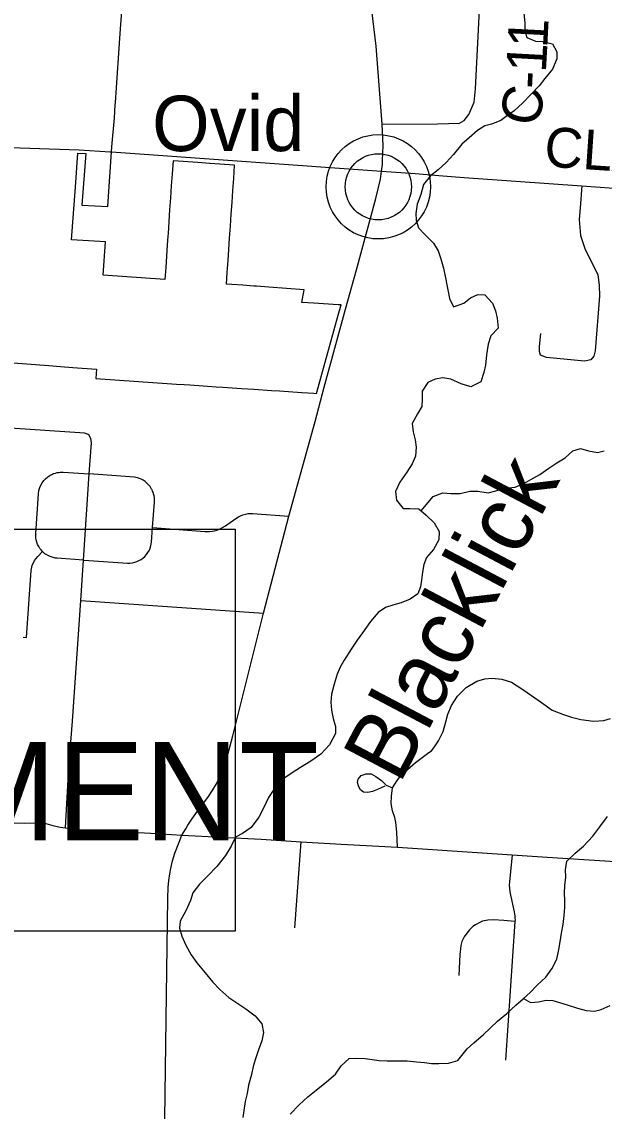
# Model space of a CAD drawing. Extents: x 208586767.6 to 208586821.4, y -134301046.9 to -134301022.9.
# Drawn here: x 208586783.069 to 208586783.899, y -134301029.209 to -134301027.656 of the extents above; entities that cross this region are included whole.
import ezdxf

# ---------------------------------------------------------------- set-up
doc = ezdxf.new("R2010")
doc.units = 0
for name, color, linetype in [('GM_X_Corporation', 7, 'Continuous'), ('GM_X_County_Road', 7, 'Continuous'), ('GM_X_County_Road_Text', 7, 'Continuous'), ('GM_X_Minor_River', 7, 'Continuous'), ('GM_X_Minor_River_Text', 7, 'Continuous'), ('GM_X_Township_Road', 7, 'Continuous'), ('GM_X_Unincorporated', 7, 'Continuous'), ('GM_X_Unincorporated_Location', 7, 'Continuous'), ('GM_X_Unincorporated_Text', 7, 'Continuous'), ('SH_Text', 7, 'Continuous')]:
    doc.layers.add(name, color=color, linetype=linetype)

msp = doc.modelspace()

# ---------------------------------------------------------------- linework, layer by layer
at = {"layer": 'GM_X_Corporation'}
msp.add_lwpolyline([(208586783.0375, -134301028.1406), (208586783.1069, -134301028.1457), (208586783.124, -134301028.147), (208586783.1414, -134301028.1483), (208586783.1752, -134301028.1508), (208586783.1743, -134301028.1644), (208586783.2892, -134301028.1721), (208586783.3002, -134301028.1729), (208586783.3081, -134301028.1734), (208586783.327, -134301028.1746), (208586783.3459, -134301028.1759), (208586783.3553, -134301028.1766), (208586783.3818, -134301028.1783), (208586783.3995, -134301028.1795), (208586783.4246, -134301028.1812), (208586783.436, -134301028.182), (208586783.4678, -134301028.1841), (208586783.4851, -134301028.1853), (208586783.489, -134301028.1855), (208586783.5199, -134301028.0739), (208586783.5238, -134301028.0594), (208586783.5197, -134301028.0591), (208586783.4849, -134301028.0567), (208586783.4681, -134301028.0556), (208586783.4711, -134301028.0376), (208586783.4209, -134301028.0339), (208586783.4032, -134301028.0327), (208586783.3995, -134301028.0324), (208586783.384, -134301028.0313), (208586783.3682, -134301028.0301), (208586783.3604, -134301028.0296), (208586783.3615, -134301028.0132), (208586783.3627, -134301027.9962), (208586783.3638, -134301027.9802), (208586783.3649, -134301027.9641), (208586783.3661, -134301027.9471), (208586783.3673, -134301027.9301), (208586783.3684, -134301027.9131), (208586783.3696, -134301027.8961), (208586783.3708, -134301027.8791), (208586783.3721, -134301027.8602), (208586783.3366, -134301027.8575), (208586783.3196, -134301027.8563), (208586783.2842, -134301027.8537), (208586783.2829, -134301027.8725), (208586783.2818, -134301027.8896), (208586783.2806, -134301027.9066), (208586783.2794, -134301027.9236), (208586783.2783, -134301027.9406), (208586783.2771, -134301027.9576), (208586783.2768, -134301027.9615), (208586783.276, -134301027.9736), (208586783.2749, -134301027.9897), (208586783.2738, -134301028.0058), (208586783.2725, -134301028.0232), (208586783.1845, -134301028.0168), (208586783.188, -134301027.9694), (208586783.1393, -134301027.9664), (208586783.145, -134301027.8912), (208586783.1486, -134301027.8428), (208586783.1486, -134301027.8428), (208586783.1598, -134301027.8435), (208586783.1541, -134301027.9169), (208586783.1913, -134301027.9191), (208586783.1972, -134301027.834), (208586783.2006, -134301027.7926), (208586783.2019, -134301027.7741), (208586783.2021, -134301027.7709), (208586783.2036, -134301027.7498), (208586783.205, -134301027.7286), (208586783.2065, -134301027.7074), (208586783.208, -134301027.6863), (208586783.2094, -134301027.6657), (208586783.2111, -134301027.6408)], dxfattribs=at)
at = {"layer": 'GM_X_County_Road'}
msp.add_line((208586783.1652, -134301027.8391), (208586783.1948, -134301027.8409), dxfattribs=at)
for points in [[(208586783.5826, -134301027.8014), (208586783.574, -134301027.6903), (208586783.5505, -134301027.4964), (208586783.5287, -134301027.2902), (208586783.5223, -134301027.2238)], [(208586783.5826, -134301027.8014), (208586783.6614, -134301027.8011), (208586783.6926, -134301027.8), (208586783.6994, -134301027.7964), (208586783.7062, -134301027.7879), (208586783.7138, -134301027.7703), (208586783.7156, -134301027.7514), (208586783.7306, -134301027.4507)], [(208586783.5817, -134301027.8687), (208586783.5829, -134301027.8591), (208586783.5831, -134301027.8531), (208586783.5838, -134301027.8322), (208586783.5826, -134301027.8014)], [(208586783.0158, -134301027.8351), (208586783.0232, -134301027.834), (208586783.1505, -134301027.8382), (208586783.1652, -134301027.8391)], [(208586783.1948, -134301027.8409), (208586783.1967, -134301027.8411), (208586783.5817, -134301027.8687)], [(208586783.4131, -134301028.4986), (208586783.4496, -134301028.3604), (208586783.4867, -134301028.2254), (208586783.4997, -134301028.1766), (208586783.5304, -134301028.0655), (208586783.5459, -134301028.0093), (208586783.5736, -134301027.9076), (208586783.5799, -134301027.8798), (208586783.5817, -134301027.8687)], [(208586783.5817, -134301027.8687), (208586783.6297, -134301027.8721), (208586783.6689, -134301027.8754), (208586783.6996, -134301027.8776)], [(208586783.6996, -134301027.8776), (208586783.773, -134301027.8829), (208586783.867, -134301027.8895), (208586783.9974, -134301027.8988), (208586784.018, -134301027.9003), (208586784.1319, -134301027.9081), (208586784.1979, -134301027.9129), (208586784.2562, -134301027.9169), (208586784.5033, -134301027.9324), (208586784.6185, -134301027.94), (208586784.7204, -134301027.9474)], [(208586783.2724, -134301029.22), (208586783.2744, -134301029.0773), (208586783.277, -134301028.9052), (208586783.2775, -134301028.89), (208586783.2784, -134301028.88), (208586783.2796, -134301028.8704), (208586783.2809, -134301028.8629), (208586783.2836, -134301028.8517), (208586783.2869, -134301028.8409), (208586783.293, -134301028.8253), (208586783.297, -134301028.8153), (208586783.3023, -134301028.8062), (208586783.3053, -134301028.8011), (208586783.311, -134301028.7924), (208586783.3169, -134301028.7845), (208586783.3349, -134301028.7601), (208586783.3411, -134301028.7508), (208586783.346, -134301028.7421), (208586783.3543, -134301028.7247), (208586783.3572, -134301028.7172), (208586783.3603, -134301028.7074), (208586783.3695, -134301028.6735), (208586783.3851, -134301028.6107), (208586783.4131, -134301028.4986)]]:
    msp.add_lwpolyline(points, dxfattribs=at)
at = {"layer": 'GM_X_Minor_River'}
for points in [[(208586783.7844, -134301027.6427), (208586783.7858, -134301027.6575), (208586783.7861, -134301027.6685), (208586783.7887, -134301027.678), (208586783.8012, -134301027.6834), (208586783.811, -134301027.6838), (208586783.8255, -134301027.6869), (208586783.8315, -134301027.6984), (208586783.8318, -134301027.7086), (208586783.8256, -134301027.723), (208586783.8145, -134301027.7366), (208586783.8065, -134301027.7468), (208586783.7943, -134301027.7592), (208586783.7824, -134301027.7717), (208586783.7706, -134301027.7826), (208586783.761, -134301027.7894), (208586783.7515, -134301027.7966), (208586783.7386, -134301027.8014), (208586783.7287, -134301027.804), (208586783.7184, -134301027.8108), (208586783.7066, -134301027.8213), (208586783.6959, -134301027.83), (208586783.6844, -134301027.8447), (208586783.6737, -134301027.8561), (208586783.6623, -134301027.8666), (208586783.6512, -134301027.8753), (208586783.6413, -134301027.8874), (208586783.6374, -134301027.9018), (208586783.6324, -134301027.9158), (208586783.6304, -134301027.929), (208586783.6311, -134301027.9385), (208586783.6344, -134301027.9496), (208586783.6431, -134301027.9591), (208586783.6555, -134301027.9713), (208586783.6623, -134301027.9824), (208586783.666, -134301027.9934), (208586783.6701, -134301028.0071), (208586783.6727, -134301028.0208), (208586783.6749, -134301028.0306), (208586783.6767, -134301028.0401), (208586783.6786, -134301028.05), (208586783.6842, -134301028.0622), (208586783.699, -134301028.0566), (208586783.7086, -134301028.0494), (208586783.7188, -134301028.0446), (208586783.7287, -134301028.045), (208586783.74, -134301028.0568), (208586783.7441, -134301028.0675), (208586783.7467, -134301028.0781), (208586783.7478, -134301028.0926), (208586783.7374, -134301028.1035), (208586783.7336, -134301028.1152), (208586783.7312, -134301028.1304), (208586783.73, -134301028.1452), (208586783.7276, -134301028.1558), (208586783.723, -134301028.1687), (208586783.7089, -134301028.1762), (208586783.6953, -134301028.1719), (208586783.6805, -134301028.165), (208586783.6691, -134301028.1631), (208586783.6581, -134301028.1649), (208586783.6475, -134301028.1701), (208586783.6394, -134301028.1822), (208586783.6397, -134301028.1932), (208586783.6389, -134301028.2039), (208586783.6328, -134301028.2145), (208586783.6255, -134301028.2281), (208586783.6265, -134301028.2402), (208586783.6295, -134301028.2516)], [(208586783.6295, -134301028.2516), (208586783.6309, -134301028.2619), (208586783.6301, -134301028.2748), (208586783.6255, -134301028.2858), (208586783.6178, -134301028.2979), (208586783.6079, -134301028.3118), (208586783.6017, -134301028.3251), (208586783.6028, -134301028.3376), (208586783.6122, -134301028.3494), (208586783.6217, -134301028.3495), (208586783.6349, -134301028.3499), (208586783.6451, -134301028.3591), (208586783.6568, -134301028.3698), (208586783.664, -134301028.3824), (208586783.6635, -134301028.3941), (208586783.6555, -134301028.4081), (208586783.6459, -134301028.4195), (208586783.6417, -134301028.4293), (208586783.6401, -134301028.4403), (208586783.6385, -134301028.4517), (208586783.6373, -134301028.4612), (208586783.6334, -134301028.471), (208586783.6224, -134301028.4789), (208586783.6094, -134301028.4841), (208586783.5992, -134301028.4867), (208586783.587, -134301028.4908), (208586783.5767, -134301028.4976), (208586783.566, -134301028.5104), (208586783.5545, -134301028.5267), (208586783.5469, -134301028.5373), (208586783.5381, -134301028.5501), (208586783.5285, -134301028.5656), (208586783.5227, -134301028.5758), (208586783.5185, -134301028.5857), (208586783.5138, -134301028.6001), (208586783.5103, -134301028.6141), (208586783.5091, -134301028.6255), (208586783.5102, -134301028.6369), (208586783.5128, -134301028.649), (208586783.5157, -134301028.6604), (208586783.516, -134301028.6703), (208586783.5076, -134301028.6862), (208586783.495, -134301028.6998), (208586783.4809, -134301028.7095), (208586783.466, -134301028.7186), (208586783.4554, -134301028.7253), (208586783.4435, -134301028.7336), (208586783.4309, -134301028.7457), (208586783.4206, -134301028.7615), (208586783.4137, -134301028.7759), (208586783.4064, -134301028.7895), (208586783.3956, -134301028.8043), (208586783.3831, -134301028.8129), (208586783.3735, -134301028.8182), (208586783.367, -134301028.8307), (208586783.359, -134301028.8443), (208586783.3467, -134301028.8598), (208586783.3341, -134301028.8734), (208586783.3219, -134301028.885), (208586783.3127, -134301028.8975), (208586783.3092, -134301028.9081), (208586783.3023, -134301028.9229), (208586783.2946, -134301028.938), (208586783.2934, -134301028.9479), (208586783.2968, -134301028.9593), (208586783.3027, -134301028.9722), (208586783.3103, -134301028.9859), (208586783.3182, -134301028.9973), (208586783.3279, -134301029.0088), (208586783.3411, -134301029.0248), (208586783.3509, -134301029.0351), (208586783.3638, -134301029.0466), (208586783.3766, -134301029.0554), (208586783.3883, -134301029.063), (208586783.4016, -134301029.0726), (208586783.411, -134301029.0841), (208586783.4132, -134301029.0966), (208586783.4108, -134301029.1083), (208586783.4062, -134301029.1212), (208586783.4012, -134301029.1356), (208586783.3985, -134301029.1451), (208586783.3961, -134301029.1564), (208586783.3918, -134301029.1716), (208586783.3899, -134301029.1834), (208586783.3871, -134301029.1947), (208586783.3852, -134301029.2076), (208586783.3836, -134301029.2178)], [(208586783.638, -134301028.3527), (208586783.6552, -134301028.3322), (208586783.6692, -134301028.3274), (208586783.6802, -134301028.3282), (208586783.6939, -134301028.3283), (208586783.7076, -134301028.325), (208586783.719, -134301028.325), (208586783.7338, -134301028.327), (208586783.7448, -134301028.3244), (208586783.7573, -134301028.3207), (208586783.7722, -134301028.3189), (208586783.7847, -134301028.3137), (208586783.7946, -134301028.3084), (208586783.8072, -134301028.3009), (208586783.8201, -134301028.2922), (208586783.8316, -134301028.2843), (208586783.8434, -134301028.2772), (208586783.8545, -134301028.2674), (208586783.8651, -134301028.2641), (208586783.8765, -134301028.2672), (208586783.8897, -134301028.2699), (208586783.8992, -134301028.2673)], [(208586783.4512, -134301029.2129), (208586783.4642, -134301029.1997), (208586783.4764, -134301029.1884), (208586783.4886, -134301029.1786), (208586783.5031, -134301029.167), (208586783.5157, -134301029.1557), (208586783.5241, -134301029.1439), (208586783.5355, -134301029.1334), (208586783.545, -134301029.1331), (208586783.5583, -134301029.1335), (208586783.5682, -134301029.1351), (208586783.578, -134301029.1363), (208586783.5898, -134301029.1371), (208586783.6016, -134301029.1368), (208586783.6183, -134301029.1369), (208586783.6315, -134301029.1385), (208586783.6429, -134301029.1393), (208586783.6528, -134301029.1405), (208586783.6634, -134301029.1406), (208586783.6771, -134301029.1403), (208586783.6904, -134301029.1362), (208586783.7038, -134301029.1196), (208586783.7133, -134301029.1113), (208586783.7271, -134301029.0996), (208586783.7366, -134301029.0902), (208586783.7469, -134301029.0804), (208586783.7603, -134301029.0695), (208586783.7732, -134301029.0574), (208586783.7835, -134301029.0484), (208586783.7935, -134301029.0393), (208586783.8034, -134301029.0291), (208586783.816, -134301029.0178), (208586783.8244, -134301029.0057), (208586783.8317, -134301028.9921), (208586783.8345, -134301028.9781), (208586783.8364, -134301028.9671), (208586783.838, -134301028.955), (208586783.8404, -134301028.9424), (208586783.842, -134301028.9299), (208586783.8432, -134301028.9182), (208586783.8429, -134301028.9079), (208586783.8426, -134301028.8981), (208586783.843, -134301028.8871), (208586783.8442, -134301028.8753), (208586783.8439, -134301028.8647), (208586783.8459, -134301028.8525), (208586783.8577, -134301028.8408), (208586783.8695, -134301028.8307), (208586783.8829, -134301028.8167), (208586783.8929, -134301028.8031), (208586783.904, -134301028.7888)], [(208586783.784, -134301029.048), (208586783.7941, -134301029.0537), (208586783.8055, -134301029.0527), (208586783.8162, -134301029.0505), (208586783.8257, -134301029.0509), (208586783.8355, -134301029.0536), (208586783.8461, -134301029.0571), (208586783.8609, -134301029.0617), (208586783.8734, -134301029.0652), (208586783.8852, -134301029.0661), (208586783.8947, -134301029.0638), (208586783.9076, -134301029.0582)]]:
    msp.add_lwpolyline(points, dxfattribs=at)
at = {"layer": 'GM_X_Township_Road'}
for p, q in [((208586783.1529, -134301028.4806), (208586783.4131, -134301028.4986)), ((208586783.4581, -134301028.9473), (208586783.4671, -134301028.8247)), ((208586783.7677, -134301028.8432), (208586783.7642, -134301028.8818))]:
    msp.add_line(p, q, dxfattribs=at)
for points in [[(208586783.867, -134301027.8895), (208586783.8648, -134301027.9211), (208586783.8634, -134301027.9375), (208586783.8652, -134301027.9601), (208586783.8713, -134301027.9788), (208586783.8899, -134301028.0165), (208586783.8921, -134301028.0313), (208586783.8926, -134301028.0467), (208586783.8861, -134301028.1246), (208586783.8841, -134301028.1322), (208586783.8799, -134301028.1378), (208586783.871, -134301028.1394), (208586783.8166, -134301028.1344), (208586783.8081, -134301028.1307), (208586783.8069, -134301028.1255), (208586783.8069, -134301028.1188), (208586783.8088, -134301028.1001)], [(208586783.1307, -134301028.8049), (208586783.1355, -134301028.7186), (208586783.141, -134301028.6526), (208586783.1529, -134301028.4806), (208586783.1566, -134301028.423), (208586783.1647, -134301028.3003), (208586783.1679, -134301028.2561), (208586783.1671, -134301028.2499), (208586783.1641, -134301028.2444), (208586783.1587, -134301028.2422), (208586783.0371, -134301028.2339), (208586782.6913, -134301028.2052)], [(208586783.1566, -134301028.423), (208586783.1192, -134301028.4205), (208586783.1163, -134301028.4201), (208586783.1132, -134301028.4195), (208586783.1089, -134301028.4181), (208586783.1052, -134301028.4162), (208586783.1016, -134301028.4139), (208586783.0981, -134301028.4109), (208586783.096, -134301028.4086), (208586783.0943, -134301028.4064), (208586783.0927, -134301028.4037), (208586783.0911, -134301028.4006), (208586783.0899, -134301028.3974), (208586783.0891, -134301028.3942), (208586783.0886, -134301028.3911), (208586783.0884, -134301028.3881), (208586783.0885, -134301028.3852), (208586783.0924, -134301028.3285), (208586783.0931, -134301028.3238), (208586783.0943, -134301028.3197), (208586783.0957, -134301028.3163), (208586783.0977, -134301028.3128), (208586783.1001, -134301028.3096), (208586783.1025, -134301028.307), (208586783.1055, -134301028.3044), (208586783.1084, -134301028.3025), (208586783.1112, -134301028.301), (208586783.114, -134301028.2998), (208586783.1165, -134301028.299), (208586783.1189, -134301028.2984), (208586783.1212, -134301028.298), (208586783.1234, -134301028.2978), (208586783.1251, -134301028.2977), (208586783.1263, -134301028.2978), (208586783.1277, -134301028.2978), (208586783.1647, -134301028.3003)], [(208586783.1566, -134301028.423), (208586783.1577, -134301028.4231), (208586783.2191, -134301028.4275), (208586783.2227, -134301028.4274), (208586783.2264, -134301028.427), (208586783.2296, -134301028.4262), (208586783.2326, -134301028.4252), (208586783.2356, -134301028.4238), (208586783.2387, -134301028.4221), (208586783.2414, -134301028.4202), (208586783.2441, -134301028.4178), (208586783.2463, -134301028.4153), (208586783.2485, -134301028.4122), (208586783.2505, -134301028.4087), (208586783.2521, -134301028.4045), (208586783.2532, -134301028.4001), (208586783.2536, -134301028.3973), (208586783.2551, -134301028.3766), (208586783.2577, -134301028.3405), (208586783.2578, -134301028.339), (208586783.2578, -134301028.3381), (208586783.2577, -134301028.3363), (208586783.2576, -134301028.3338), (208586783.2572, -134301028.3315), (208586783.2565, -134301028.3285), (208586783.2557, -134301028.3261), (208586783.2552, -134301028.3248), (208586783.2543, -134301028.3231), (208586783.2537, -134301028.3218), (208586783.2526, -134301028.3199), (208586783.2515, -134301028.3183), (208586783.2505, -134301028.317), (208586783.2485, -134301028.3147), (208586783.247, -134301028.3133), (208586783.2444, -134301028.3111), (208586783.2416, -134301028.3093), (208586783.2388, -134301028.3078), (208586783.2362, -134301028.3067), (208586783.2335, -134301028.3058), (208586783.2312, -134301028.3053), (208586783.2292, -134301028.305), (208586783.1647, -134301028.3003)], [(208586783.2551, -134301028.3766), (208586783.3298, -134301028.3825), (208586783.3328, -134301028.3825), (208586783.3363, -134301028.3823), (208586783.34, -134301028.3818), (208586783.3432, -134301028.3812), (208586783.3466, -134301028.3802), (208586783.3506, -134301028.3788), (208586783.3548, -134301028.3767), (208586783.3589, -134301028.3742), (208586783.3609, -134301028.3728), (208586783.3753, -134301028.3626), (208586783.3775, -134301028.3613), (208586783.3806, -134301028.3598), (208586783.3839, -134301028.3585), (208586783.3879, -134301028.3574), (208586783.3915, -134301028.3568), (208586783.3944, -134301028.3565), (208586783.3976, -134301028.3565), (208586783.4496, -134301028.3604)], [(208586783.0704, -134301028.5329), (208586783.0751, -134301028.5332), (208586783.0818, -134301028.4377), (208586783.0833, -134301028.4308), (208586783.0865, -134301028.4238), (208586783.0913, -134301028.4178), (208586783.0981, -134301028.4109)], [(208586783.6045, -134301028.8323), (208586783.6032, -134301028.8107), (208586783.6021, -134301028.7972), (208586783.6006, -134301028.7901), (208586783.597, -134301028.7806), (208586783.5952, -134301028.77), (208586783.5958, -134301028.7598), (208586783.597, -134301028.7475), (208586783.6037, -134301028.7373), (208586783.6103, -134301028.7285), (208586783.6298, -134301028.7116), (208586783.6491, -134301028.6974), (208586783.6529, -134301028.695), (208586783.6564, -134301028.6905), (208586783.663, -134301028.6806), (208586783.6694, -134301028.6676), (208586783.6732, -134301028.6536), (208586783.6762, -134301028.6428), (208586783.6812, -134301028.6305), (208586783.6899, -134301028.617), (208586783.7022, -134301028.6047), (208586783.7173, -134301028.5958), (208586783.7291, -134301028.5922), (208586783.739, -134301028.5912), (208586783.7529, -134301028.5929), (208586783.7668, -134301028.5971), (208586783.7829, -134301028.6076), (208586783.8065, -134301028.6236), (208586783.8249, -134301028.6368), (208586783.8413, -134301028.6433), (208586783.8527, -134301028.6471), (208586783.866, -134301028.6505), (208586783.8837, -134301028.6528), (208586783.8986, -134301028.6518), (208586783.9081, -134301028.6488)], [(208586783.5863, -134301028.7454), (208586783.576, -134301028.7499), (208586783.5687, -134301028.7531), (208586783.5619, -134301028.7542), (208586783.556, -134301028.754), (208586783.5515, -134301028.7508), (208586783.549, -134301028.7461), (208586783.5475, -134301028.74), (208586783.5482, -134301028.7353), (208586783.5524, -134301028.7301), (208586783.5599, -134301028.7276), (208586783.5669, -134301028.7278), (208586783.5734, -134301028.7316), (208586783.5813, -134301028.7375), (208586783.5882, -134301028.7441), (208586783.597, -134301028.7475)], [(208586783.0579, -134301028.7977), (208586783.0726, -134301028.7983), (208586783.0893, -134301028.7974), (208586783.0961, -134301028.7976), (208586783.1027, -134301028.7985), (208586783.113, -134301028.8015), (208586783.1235, -134301028.8038), (208586783.1307, -134301028.8049), (208586783.151, -134301028.807), (208586783.2526, -134301028.8124), (208586783.297, -134301028.8153)], [(208586783.297, -134301028.8153), (208586783.41, -134301028.8208), (208586783.417, -134301028.8213)], [(208586783.417, -134301028.8213), (208586783.4671, -134301028.8247), (208586783.5242, -134301028.828), (208586783.6045, -134301028.8323), (208586783.725, -134301028.8404), (208586783.7677, -134301028.8432), (208586783.818, -134301028.8464)], [(208586783.818, -134301028.8464), (208586784.1697, -134301028.8688), (208586784.3008, -134301028.8794), (208586784.5289, -134301028.8974), (208586784.6503, -134301028.9073)], [(208586783.7642, -134301028.8818), (208586783.7638, -134301028.8865), (208586783.764, -134301028.8906), (208586783.7645, -134301028.8959), (208586783.765, -134301028.8985), (208586783.7669, -134301028.9068), (208586783.7687, -134301028.9161), (208586783.7706, -134301028.9243), (208586783.7715, -134301028.9302), (208586783.7719, -134301028.9338), (208586783.772, -134301028.9361), (208586783.7719, -134301028.9381), (208586783.7583, -134301029.136)], [(208586783.7719, -134301028.9381), (208586783.7561, -134301028.9367), (208586783.7412, -134301028.9361), (208586783.7331, -134301028.9366), (208586783.7258, -134301028.938), (208586783.7207, -134301028.94), (208586783.7154, -134301028.943), (208586783.7118, -134301028.9456), (208586783.7068, -134301028.9501), (208586783.703, -134301028.9547), (208586783.6994, -134301028.9603), (208586783.6963, -134301028.967), (208586783.6948, -134301028.9723), (208586783.694, -134301028.9774), (208586783.6934, -134301028.9851), (208586783.6918, -134301029.0151)]]:
    msp.add_lwpolyline(points, dxfattribs=at)
at = {"layer": 'GM_X_Unincorporated'}
for radius in [0.0744, 0.0472]:
    msp.add_circle((208586783.577, -134301027.8909), radius, dxfattribs=at)
at = {"layer": 'GM_X_Unincorporated_Location'}
msp.add_line((208586783.577, -134301027.8909), (208586783.577, -134301027.8909), dxfattribs=at)
at = {"layer": 'SH_Text'}
msp.add_lwpolyline([(208586781.104, -134301028.379), (208586783.373, -134301028.379), (208586783.373, -134301028.9519), (208586781.104, -134301028.9519)], close=True, dxfattribs=at)

# ---------------------------------------------------------------- texts
at = {"layer": 'GM_X_County_Road_Text'}
for s, height, rotation, p in [('1', 0.0568, 87.0466, (208586783.8178, -134301027.6939)), ('1', 0.0568, 86.8969, (208586783.8159, -134301027.729)), ('-', 0.0568, 87.3684, (208586783.8148, -134301027.7522)), ('C', 0.0568, 79.3499, (208586783.8052, -134301027.8067)), ('CLARK', 0.05682, 356.1481, (208586783.8124, -134301027.8618))]:
    msp.add_text(s, height=height, rotation=rotation, dxfattribs=at).set_placement(p)
at = {"layer": 'GM_X_Minor_River_Text'}
msp.add_text('Blacklick', height=0.09469, rotation=62.1927, dxfattribs=at).set_placement((208586783.6071, -134301028.7443))
at = {"layer": 'GM_X_Unincorporated_Text'}
msp.add_text('Ovid', height=0.07898, rotation=0, dxfattribs=at).set_placement((208586783.2544, -134301027.84))
at = {"layer": 'SH_Text'}
msp.add_text('CULVERT REPLACEMENT', height=0.14, dxfattribs=at).set_placement((208586781.1624, -134301028.8224))

doc.saveas('drawing.dxf')
